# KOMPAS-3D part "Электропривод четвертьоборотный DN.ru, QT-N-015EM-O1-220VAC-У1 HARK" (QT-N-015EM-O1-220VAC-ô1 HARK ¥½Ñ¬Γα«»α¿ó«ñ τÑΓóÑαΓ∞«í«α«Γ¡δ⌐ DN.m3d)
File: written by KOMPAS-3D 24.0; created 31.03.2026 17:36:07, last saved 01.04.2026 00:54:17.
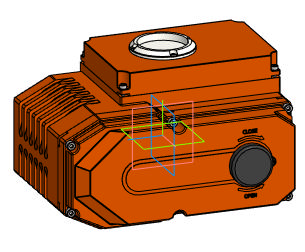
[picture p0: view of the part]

Document properties: Автор: DN.RU; Полное имя файла: D:\PROJECT CAD\DN.RU\...195\Исходники\220В\QT-N-015EM-O1-220VAC-У1 HARK Электропривод четвертьоборотный DN.ru\QT-N-015EM-O1-220VAC-У1 HARK Электропривод четвертьоборотный DN.m3d

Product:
- Body: Твердое тело1  | qty 1
    Масса: 18.642152
- Part/product: Электропривод четвертьоборотный DN.ru  | designation QT-N-015EM-O1-220VAC-У1 HARK
    Масса: 4.6
    Раздел спецификации: Прочие изделия
    Комментарий: D300-14487
    Примечание: D300-14486
    additional columns: Сталь

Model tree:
1. Твердое тело1  (labels: Твердое тело1)

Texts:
  QT-N-015EM-O1-220VAC-У1 HARK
